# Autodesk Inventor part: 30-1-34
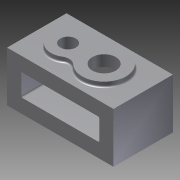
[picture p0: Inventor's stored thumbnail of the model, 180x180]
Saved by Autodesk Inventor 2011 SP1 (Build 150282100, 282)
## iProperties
Created: 2014-02
Part Number: 30-1-34
Document SubType Name: Modeling
Designer: Administrator
Density: 1 g/cm^3
Author: Administrator
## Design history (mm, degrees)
sketch "草图1"
  geometry: L1 (-34, 19)-(34, 19); L2 (34, 19)-(34, -19); L3 (34, -19)-(-34, -19); L4 (-34, -19)-(-34, 19); 3 further points
  constraints: 8 end point, 2 midpoint, 2 parallel, 1 horizontal, 1 horizontal alignment, 1 perpendicular, 1 vertical alignment
  dimensions: "d0" = 38 distance of L1.end L2.end; "d1" = 68 distance of L1.start L1.end
extrude "拉伸1" new body sketch "草图1" distance "d2" = 32; taper "d3" = 0 deg
sketch "草图2"
  geometry: L1 (34, 19)-(34, -19) reference; L2 (-34, -19)-(-34, 19) reference; A1 r 11 centre (-14, 0) between (-8.12, 9.297) and (-8.12, -9.297); A2 r 14 centre (9, 0) between (-0.739, -10.057) and (-0.739, 10.057); A3 r 6 centre (-4.913, 14.368) between (-8.12, 9.297) and (-0.739, 10.057); A4 r 6 centre (-4.913, -14.368) between (-0.739, -10.057) and (-8.12, -9.297); 1 further point
  constraints: 8 point on circle, 4 centre point, 4 tangent, 1 equal radius
  dimensions: "d4" = 22 diameter of A1; "d5" = 20 distance from line of L2 A1.centre; "d6" = 28 diameter of A2; "d7" = 25 distance from line of L1 A2.centre; "d8" = 6 radius of A3
extrude "拉伸2" join sketch "草图2" distance "d9" = 3; taper "d10" = 0 deg
hole "Hole1" diameter "d13" = 10; stored, may be unused: countersink angle "d17" = 90 deg, drill point angle "d19" = 0 deg; dims "d11" = 10, "d12" = 10, "d14" = 6, "d15" = 4, "d16" = 2, "d18" = 7
hole "Hole2" diameter "d22" = 15; stored, may be unused: countersink angle "d26" = 90 deg, drill point angle "d28" = 0 deg; dims "d20" = 10, "d21" = 10, "d23" = 6, "d24" = 4, "d25" = 2, "d27" = 7
sketch "草图3"
  geometry: L1 (-39, 15)-(21, 15); L2 (21, 15)-(21, -15); L3 (21, -15)-(-39, -15); L4 (-39, -15)-(-39, 15); C1 r 7.5 at (0, 0) reference; 3 further points
  constraints: 8 end point, 2 midpoint, 2 parallel, 1 horizontal, 1 horizontal alignment, 1 perpendicular, 1 vertical alignment
  dimensions: "d29" = 30 distance of L1.end L2.end; "d30" = 60 distance of L1.start L1.end
extrude "拉伸3" cut sketch "草图3" distance "d31" = 24; taper "d32" = 0 deg
sketch "草图4"
  geometry: L1 (68, 32)-(0, 32) reference; L2 (0, 0)-(0, 32) reference; L3 (9, 23)-(59, 23); L4 (59, 23)-(59, 9); L5 (59, 9)-(9, 9); L6 (9, 9)-(9, 23); 5 further points
  constraints: 8 end point, 4 midpoint, 2 parallel, 1 horizontal, 1 horizontal alignment, 1 perpendicular, 1 vertical alignment
  dimensions: "d33" = 50 distance of L4.end L5.end; "d34" = 14 distance of L3.end L4.end
extrude "拉伸4" cut sketch "草图4" distance "d35" = 4; taper "d36" = 0 deg
sketch "草图5"
  geometry: C1 r 7.5 at (0, 0) reference; C2 r 7.5 at (0, 0); 1 further point
  constraints: 1 centre point, 1 coincident, 1 concentric
extrude "拉伸5" cut sketch "草图5" stored distance "d37" = 4; taper "d38" = 0 deg
sketch "草图6"
  geometry: L1 (34, -19)-(34, 19) reference; C1 r 6.5 at (14, 8); C2 r 5 at (14, 0) reference; 1 further point
  constraints: 1 centre point
  dimensions: "d39" = 13 diameter of C1; "d40" = 20 distance from line of L1 C1.centre; "d41" = 8 distance of C1.centre C2.centre
extrude "拉伸6" join sketch "草图6" distance "d42" = 3; taper "d43" = 0 deg
hole "Hole3" diameter "d46" = 7; stored, may be unused: countersink angle "d50" = 90 deg, drill point angle "d52" = 0 deg; dims "d44" = 10, "d45" = 10, "d47" = 6, "d48" = 4, "d49" = 2, "d51" = 10
fillet "圆角1" dims "d53" = 1
node "实体1"
